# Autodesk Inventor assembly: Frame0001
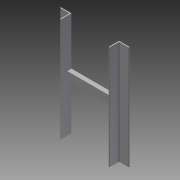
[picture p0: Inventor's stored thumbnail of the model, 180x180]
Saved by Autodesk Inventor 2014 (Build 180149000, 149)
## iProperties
Created: 2009-11
Part Number: Frame0001
Document SubType Name: Assembly
Designer: pokornp
Mass: 297817 g
Surface Area: 35410.7 cm^2
Volume: 37890.2 cm^3
Density: 7.86 g/cm^3
_FrameDoc: Frame Assembly
_Version: 15.0.0
Author: pokornp
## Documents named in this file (5)
- C:\Users\iTools\Desktop\tutorial files\Frame Analysis 1\Assembly2\Frame\Frame0001.iam
- C:\Users\iTools\Desktop\tutorial files\Frame Analysis 1\Assembly2\Frame\Skeleton0001.ipt
- C:\Users\iTools\Desktop\tutorial files\Frame Analysis 1\Assembly2\Frame\DIN L200x200x18 00000001.ipt
- C:\Users\iTools\Desktop\tutorial files\Frame Analysis 1\Assembly2\Frame\DIN L200x200x18 00000002.ipt
- C:\Users\iTools\Desktop\tutorial files\Frame Analysis 1\Assembly2\Frame\DIN 150 x 80 00000003.ipt
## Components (4 placed, 4 different names)
1. Frame Reference Model
2. DIN L200x200x18 00000001:1
3. DIN L200x200x18 00000002:1
4. DIN 150 x 80 00000003:1
